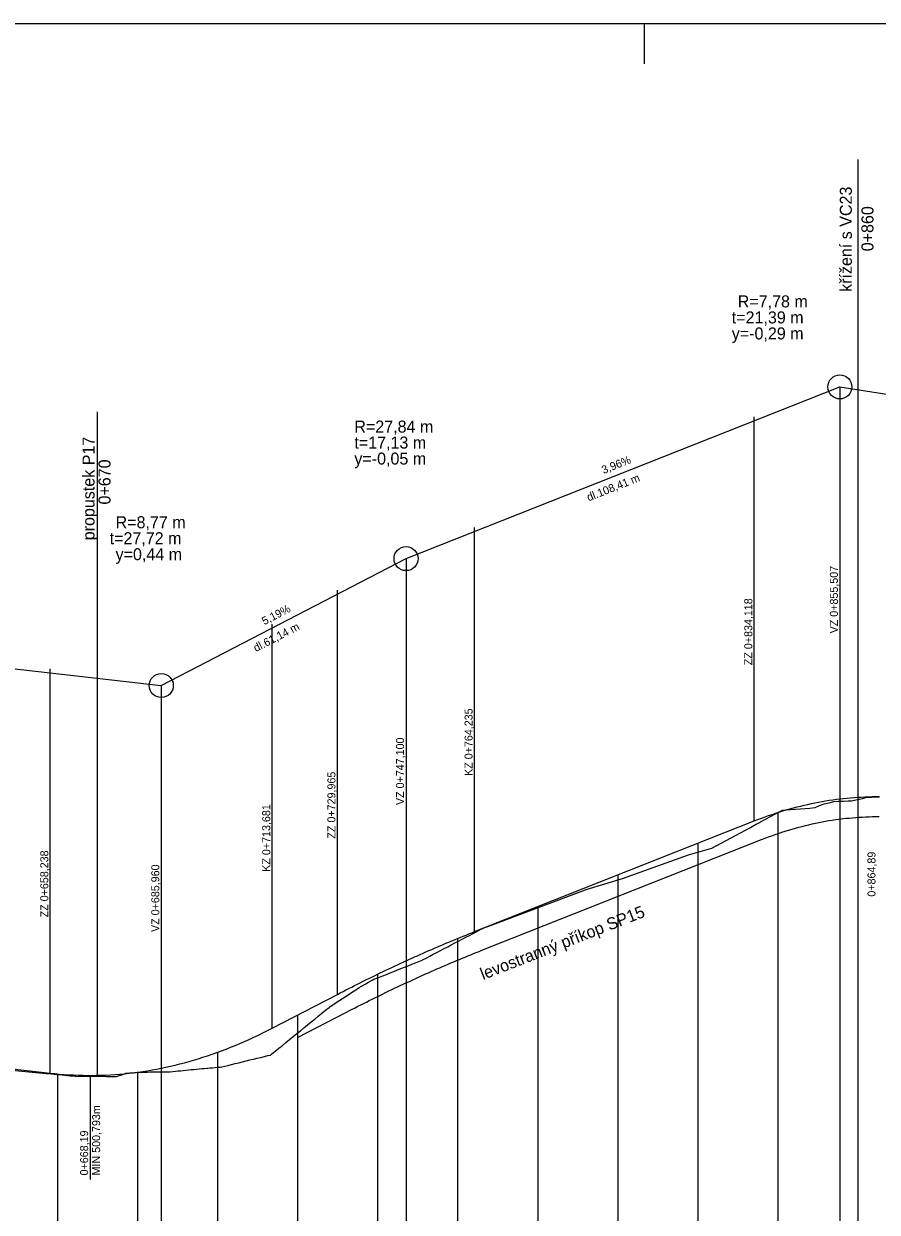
# Model space of a CAD drawing. Extents: x -632716 to -629545, y -1094726 to -1088285.
# Drawn here: x -631800.3 to -631587.1, y -1090081.9 to -1089784.9 of the extents above; entities that cross this region are included whole.
import ezdxf

# ---------------------------------------------------------------- set-up
doc = ezdxf.new("R2010")
doc.units = 0
for name, color, linetype in [('20', 7, 'Continuous'), ('Default', 7, 'Continuous'), ('formát', 7, 'Continuous'), ('PŘÍKOP', 7, 'Continuous'), ('SKLONY_NIVELETA', 7, 'Continuous'), ('SKLONY_POPIS', 7, 'Continuous'), ('TECNY_NIVELETA', 7, 'Continuous'), ('VOZOVKA', 7, 'Continuous')]:
    doc.layers.add(name, color=color, linetype=linetype)

msp = doc.modelspace()

# ---------------------------------------------------------------- linework, layer by layer
at = {"layer": '20'}
for points in [[(-631591.95, -1089978.18), (-631591.95, -1090205.62), (-631591.95, -1090255.62), (-631591.95, -1090195.62)], [(-631611.95, -1089982.01), (-631611.95, -1090205.62), (-631611.95, -1090255.62), (-631611.95, -1090195.62)], [(-631631.95, -1089989.71), (-631631.95, -1090205.62), (-631631.95, -1090255.62), (-631631.95, -1090195.62)], [(-631651.95, -1089997.62), (-631651.95, -1090205.62), (-631651.95, -1090255.62), (-631651.95, -1090195.62)], [(-631671.95, -1090005.54), (-631671.95, -1090205.62), (-631671.95, -1090255.62), (-631671.95, -1090195.62)], [(-631691.95, -1090013.48), (-631691.95, -1090205.62), (-631691.95, -1090255.62), (-631691.95, -1090195.62)], [(-631711.95, -1090022.42), (-631711.95, -1090205.62), (-631711.95, -1090255.62), (-631711.95, -1090195.62)], [(-631731.95, -1090032.62), (-631731.95, -1090205.62), (-631731.95, -1090255.62), (-631731.95, -1090195.62)], [(-631751.95, -1090041.93), (-631751.95, -1090205.62), (-631751.95, -1090255.62), (-631751.95, -1090195.62)], [(-631791.95, -1090047.31), (-631791.95, -1090205.62), (-631791.95, -1090255.62), (-631791.95, -1090195.62)], [(-631771.95, -1090046.9), (-631771.95, -1090205.62), (-631771.95, -1090255.62), (-631771.95, -1090195.62)]]:
    msp.add_lwpolyline(points, dxfattribs=at)
at = {"layer": 'Default'}
for p, q in [((-631687.72, -1090011.77), (-631617.84, -1089984.12)), ((-631738.27, -1090035.9), (-631721.99, -1090027.45)), ((-631847.6, -1090041.02), (-631793.72, -1090047.13))]:
    msp.add_line(p, q, dxfattribs=at)
for points in [[(-631617.84, -1089984.12), (-631616.94, -1089983.77), (-631616.05, -1089983.43), (-631615.16, -1089983.11), (-631614.27, -1089982.79), (-631613.38, -1089982.48), (-631612.49, -1089982.19), (-631611.6, -1089981.9), (-631610.71, -1089981.62), (-631609.82, -1089981.36), (-631608.92, -1089981.1), (-631608.03, -1089980.86), (-631607.14, -1089980.62), (-631606.25, -1089980.4), (-631605.36, -1089980.18), (-631604.47, -1089979.98), (-631603.58, -1089979.78), (-631602.69, -1089979.6), (-631601.79, -1089979.42), (-631600.9, -1089979.26), (-631600.01, -1089979.11), (-631599.12, -1089978.96), (-631598.23, -1089978.83), (-631597.34, -1089978.71), (-631595.56, -1089978.49), (-631594.66, -1089978.4), (-631593.77, -1089978.32), (-631592.88, -1089978.25), (-631591.99, -1089978.18), (-631591.1, -1089978.13), (-631590.21, -1089978.09), (-631589.32, -1089978.06), (-631588.43, -1089978.04), (-631587.53, -1089978.03), (-631586.64, -1089978.03)], [(-631721.99, -1090027.45), (-631721.27, -1090027.08), (-631720.56, -1090026.71), (-631719.85, -1090026.34), (-631719.13, -1090025.98), (-631718.42, -1090025.62), (-631717.7, -1090025.26), (-631716.99, -1090024.9), (-631716.28, -1090024.54), (-631715.56, -1090024.19), (-631714.85, -1090023.83), (-631714.14, -1090023.48), (-631713.42, -1090023.13), (-631712.71, -1090022.79), (-631711.99, -1090022.44), (-631711.28, -1090022.1), (-631710.57, -1090021.75), (-631709.85, -1090021.41), (-631709.14, -1090021.07), (-631708.42, -1090020.74), (-631707.71, -1090020.4), (-631707, -1090020.07), (-631706.28, -1090019.74), (-631705.57, -1090019.41), (-631704.14, -1090018.76), (-631703.43, -1090018.43), (-631702.71, -1090018.11), (-631702, -1090017.79), (-631701.28, -1090017.47), (-631700.57, -1090017.16), (-631699.86, -1090016.84), (-631699.14, -1090016.53), (-631698.43, -1090016.22), (-631697.71, -1090015.91), (-631697, -1090015.6), (-631696.29, -1090015.3), (-631695.57, -1090014.99), (-631694.86, -1090014.69), (-631694.14, -1090014.39), (-631693.43, -1090014.09), (-631692.72, -1090013.8), (-631692, -1090013.5), (-631691.29, -1090013.21), (-631690.57, -1090012.92), (-631689.86, -1090012.63), (-631689.15, -1090012.34), (-631688.43, -1090012.06), (-631687.72, -1090011.77)], [(-631793.72, -1090047.13), (-631792.56, -1090047.26), (-631791.41, -1090047.36), (-631790.25, -1090047.46), (-631789.1, -1090047.53), (-631787.94, -1090047.6), (-631786.78, -1090047.64), (-631785.63, -1090047.68), (-631784.47, -1090047.69), (-631783.32, -1090047.7), (-631782.16, -1090047.68), (-631781.01, -1090047.65), (-631779.85, -1090047.61), (-631778.7, -1090047.55), (-631777.54, -1090047.48), (-631776.39, -1090047.39), (-631775.23, -1090047.28), (-631774.08, -1090047.16), (-631772.92, -1090047.03), (-631771.77, -1090046.88), (-631770.61, -1090046.71), (-631769.46, -1090046.53), (-631768.3, -1090046.33), (-631767.15, -1090046.12), (-631764.84, -1090045.65), (-631763.68, -1090045.4), (-631762.53, -1090045.12), (-631761.37, -1090044.84), (-631760.22, -1090044.53), (-631759.06, -1090044.22), (-631757.91, -1090043.88), (-631756.75, -1090043.54), (-631755.6, -1090043.17), (-631754.44, -1090042.79), (-631753.29, -1090042.4), (-631752.13, -1090041.99), (-631750.98, -1090041.57), (-631749.82, -1090041.13), (-631748.67, -1090040.67), (-631747.51, -1090040.2), (-631746.36, -1090039.72), (-631745.2, -1090039.22), (-631744.05, -1090038.7), (-631742.89, -1090038.17), (-631741.74, -1090037.62), (-631740.58, -1090037.06), (-631739.43, -1090036.49), (-631738.27, -1090035.9)]]:
    msp.add_lwpolyline(points, dxfattribs=at)
at = {"layer": 'formát'}
msp.add_line((-631645.24, -1089794.9), (-631645.24, -1089784.9), dxfattribs=at)
msp.add_lwpolyline([(-632546.83, -1090378.9), (-629545.24, -1090378.9), (-629545.24, -1089784.9), (-632546.83, -1089784.9)], close=True, dxfattribs=at)
at = {"layer": 'PŘÍKOP'}
for p, q in [((-631685.88, -1090016.42), (-631616, -1089988.77)), ((-631731.95, -1090038.25), (-631719.69, -1090031.88))]:
    msp.add_line(p, q, dxfattribs=at)
for points in [[(-631616.02, -1089988.78), (-631615.15, -1089988.44), (-631614.31, -1089988.12), (-631613.46, -1089987.81), (-631612.62, -1089987.51), (-631611.78, -1089987.22), (-631610.93, -1089986.94), (-631610.09, -1089986.67), (-631609.25, -1089986.41), (-631608.41, -1089986.16), (-631607.57, -1089985.92), (-631606.73, -1089985.68), (-631605.89, -1089985.46), (-631605.05, -1089985.25), (-631604.21, -1089985.05), (-631603.38, -1089984.86), (-631602.54, -1089984.67), (-631601.7, -1089984.5), (-631600.86, -1089984.34), (-631600.03, -1089984.18), (-631599.19, -1089984.04), (-631598.35, -1089983.9), (-631597.52, -1089983.78), (-631596.7, -1089983.67), (-631595, -1089983.46), (-631594.18, -1089983.38), (-631593.34, -1089983.3), (-631592.51, -1089983.23), (-631591.67, -1089983.17), (-631590.84, -1089983.13), (-631590.01, -1089983.09), (-631589.17, -1089983.06), (-631588.34, -1089983.04), (-631587.5, -1089983.03), (-631586.67, -1089983.03)], [(-631719.69, -1090031.89), (-631718.98, -1090031.52), (-631718.28, -1090031.16), (-631717.57, -1090030.8), (-631716.87, -1090030.44), (-631716.16, -1090030.08), (-631715.46, -1090029.72), (-631714.75, -1090029.37), (-631714.05, -1090029.02), (-631713.34, -1090028.67), (-631712.64, -1090028.32), (-631711.93, -1090027.97), (-631711.23, -1090027.63), (-631710.52, -1090027.28), (-631709.82, -1090026.94), (-631709.11, -1090026.6), (-631708.41, -1090026.27), (-631707.71, -1090025.93), (-631707, -1090025.6), (-631706.3, -1090025.26), (-631705.59, -1090024.93), (-631704.89, -1090024.6), (-631704.18, -1090024.28), (-631703.48, -1090023.95), (-631702.07, -1090023.31), (-631701.37, -1090022.99), (-631700.66, -1090022.67), (-631699.96, -1090022.36), (-631699.25, -1090022.04), (-631698.55, -1090021.73), (-631697.84, -1090021.42), (-631697.14, -1090021.11), (-631696.44, -1090020.81), (-631695.73, -1090020.5), (-631695.03, -1090020.2), (-631694.32, -1090019.9), (-631693.62, -1090019.6), (-631692.92, -1090019.3), (-631692.21, -1090019), (-631691.51, -1090018.71), (-631690.8, -1090018.42), (-631690.1, -1090018.13), (-631689.4, -1090017.84), (-631688.69, -1090017.55), (-631687.99, -1090017.27), (-631687.29, -1090016.98), (-631686.58, -1090016.7), (-631685.87, -1090016.42)]]:
    msp.add_lwpolyline(points, dxfattribs=at)
at = {"layer": 'SKLONY_NIVELETA'}
for p, q in [((-631591.95, -1089818.79), (-631591.95, -1089978.18)), ((-631704.85, -1089918.56), (-631596.45, -1089875.65)), ((-631596.45, -1089875.65), (-631596.45, -1090255.62)), ((-631596.45, -1089875.65), (-631534.11, -1089885.28)), ((-631765.99, -1089950.28), (-631704.85, -1089918.56)), ((-631704.85, -1089918.56), (-631704.85, -1090255.62)), ((-631884.73, -1089936.8), (-631765.99, -1089950.28)), ((-631765.99, -1089950.28), (-631765.99, -1090255.62)), ((-631687.72, -1090011.77), (-631617.84, -1089984.12)), ((-631738.27, -1090035.9), (-631721.99, -1090027.45)), ((-631847.6, -1090041.02), (-631793.72, -1090047.13))]:
    msp.add_line(p, q, dxfattribs=at)
for points in [[(-631617.84, -1089984.12), (-631616.94, -1089983.77), (-631616.05, -1089983.43), (-631615.16, -1089983.11), (-631614.27, -1089982.79), (-631613.38, -1089982.48), (-631612.49, -1089982.19), (-631611.6, -1089981.9), (-631610.71, -1089981.62), (-631609.82, -1089981.36), (-631608.92, -1089981.1), (-631608.03, -1089980.86), (-631607.14, -1089980.62), (-631606.25, -1089980.4), (-631605.36, -1089980.18), (-631604.47, -1089979.98), (-631603.58, -1089979.78), (-631602.69, -1089979.6), (-631601.79, -1089979.42), (-631600.9, -1089979.26), (-631600.01, -1089979.11), (-631599.12, -1089978.96), (-631598.23, -1089978.83), (-631597.34, -1089978.71), (-631595.56, -1089978.49), (-631594.66, -1089978.4), (-631593.77, -1089978.32), (-631592.88, -1089978.25), (-631591.99, -1089978.18), (-631591.1, -1089978.13), (-631590.21, -1089978.09), (-631589.32, -1089978.06), (-631588.43, -1089978.04), (-631587.53, -1089978.03), (-631586.64, -1089978.03)], [(-631721.99, -1090027.45), (-631721.27, -1090027.08), (-631720.56, -1090026.71), (-631719.85, -1090026.34), (-631719.13, -1090025.98), (-631718.42, -1090025.62), (-631717.7, -1090025.26), (-631716.99, -1090024.9), (-631716.28, -1090024.54), (-631715.56, -1090024.19), (-631714.85, -1090023.83), (-631714.14, -1090023.48), (-631713.42, -1090023.13), (-631712.71, -1090022.79), (-631711.99, -1090022.44), (-631711.28, -1090022.1), (-631710.57, -1090021.75), (-631709.85, -1090021.41), (-631709.14, -1090021.07), (-631708.42, -1090020.74), (-631707.71, -1090020.4), (-631707, -1090020.07), (-631706.28, -1090019.74), (-631705.57, -1090019.41), (-631704.14, -1090018.76), (-631703.43, -1090018.43), (-631702.71, -1090018.11), (-631702, -1090017.79), (-631701.28, -1090017.47), (-631700.57, -1090017.16), (-631699.86, -1090016.84), (-631699.14, -1090016.53), (-631698.43, -1090016.22), (-631697.71, -1090015.91), (-631697, -1090015.6), (-631696.29, -1090015.3), (-631695.57, -1090014.99), (-631694.86, -1090014.69), (-631694.14, -1090014.39), (-631693.43, -1090014.09), (-631692.72, -1090013.8), (-631692, -1090013.5), (-631691.29, -1090013.21), (-631690.57, -1090012.92), (-631689.86, -1090012.63), (-631689.15, -1090012.34), (-631688.43, -1090012.06), (-631687.72, -1090011.77)], [(-631793.72, -1090047.13), (-631792.56, -1090047.26), (-631791.41, -1090047.36), (-631790.25, -1090047.46), (-631789.1, -1090047.53), (-631787.94, -1090047.6), (-631786.78, -1090047.64), (-631785.63, -1090047.68), (-631784.47, -1090047.69), (-631783.32, -1090047.7), (-631782.16, -1090047.68), (-631781.01, -1090047.65), (-631779.85, -1090047.61), (-631778.7, -1090047.55), (-631777.54, -1090047.48), (-631776.39, -1090047.39), (-631775.23, -1090047.28), (-631774.08, -1090047.16), (-631772.92, -1090047.03), (-631771.77, -1090046.88), (-631770.61, -1090046.71), (-631769.46, -1090046.53), (-631768.3, -1090046.33), (-631767.15, -1090046.12), (-631764.84, -1090045.65), (-631763.68, -1090045.4), (-631762.53, -1090045.12), (-631761.37, -1090044.84), (-631760.22, -1090044.53), (-631759.06, -1090044.22), (-631757.91, -1090043.88), (-631756.75, -1090043.54), (-631755.6, -1090043.17), (-631754.44, -1090042.79), (-631753.29, -1090042.4), (-631752.13, -1090041.99), (-631750.98, -1090041.57), (-631749.82, -1090041.13), (-631748.67, -1090040.67), (-631747.51, -1090040.2), (-631746.36, -1090039.72), (-631745.2, -1090039.22), (-631744.05, -1090038.7), (-631742.89, -1090038.17), (-631741.74, -1090037.62), (-631740.58, -1090037.06), (-631739.43, -1090036.49), (-631738.27, -1090035.9)]]:
    msp.add_lwpolyline(points, dxfattribs=at)
for centre in [(-631596.45, -1089875.65), (-631704.85, -1089918.56), (-631765.99, -1089950.28)]:
    msp.add_circle(centre, 3, dxfattribs=at)
at = {"layer": 'TECNY_NIVELETA'}
for p, q in [((-631596.45, -1089875.65), (-631596.45, -1089875.65)), ((-631781.95, -1090047.68), (-631781.95, -1089881.89)), ((-631617.84, -1089984.12), (-631617.84, -1089883.12)), ((-631687.72, -1090011.77), (-631687.72, -1089910.77)), ((-631704.85, -1089918.56), (-631704.85, -1089918.56)), ((-631721.99, -1090027.45), (-631721.99, -1089926.45)), ((-631738.27, -1090035.9), (-631738.27, -1089934.9)), ((-631793.72, -1090047.13), (-631793.72, -1089946.13)), ((-631765.99, -1089950.28), (-631765.99, -1089950.28)), ((-631783.77, -1090047.7), (-631783.77, -1090073.7))]:
    msp.add_line(p, q, dxfattribs=at)
at = {"layer": 'VOZOVKA'}
msp.add_lwpolyline([(-631821.69, -1090044.62), (-631794.79, -1090047.19), (-631794.12, -1090047.25), (-631793.45, -1090047.32), (-631792.79, -1090047.38), (-631792.12, -1090047.45), (-631791.45, -1090047.51), (-631790.79, -1090047.58), (-631790.12, -1090047.64), (-631789.45, -1090047.71), (-631788.79, -1090047.78), (-631788.12, -1090047.85), (-631787.45, -1090047.93), (-631787.36, -1090047.94), (-631786.79, -1090047.92), (-631786.12, -1090047.9), (-631785.45, -1090047.89), (-631784.79, -1090047.88), (-631784.22, -1090047.87), (-631784.15, -1090047.87), (-631783.51, -1090047.87), (-631782.87, -1090047.88), (-631782.24, -1090047.89), (-631781.6, -1090047.9), (-631780.96, -1090047.91), (-631780.32, -1090047.92), (-631779.69, -1090047.94), (-631779.05, -1090047.96), (-631778.41, -1090047.97), (-631777.77, -1090047.99), (-631777.24, -1090048.01), (-631777.14, -1090047.98), (-631776.5, -1090047.76), (-631775.86, -1090047.55), (-631775.39, -1090047.39), (-631775.22, -1090047.32), (-631774.82, -1090047.14), (-631774.59, -1090047.12), (-631773.95, -1090047.07), (-631773.31, -1090047.02), (-631772.67, -1090046.97), (-631772.04, -1090046.92), (-631771.68, -1090046.9), (-631771.4, -1090046.89), (-631770.76, -1090046.88), (-631770.13, -1090046.87), (-631769.49, -1090046.86), (-631768.85, -1090046.85), (-631768.21, -1090046.85), (-631768.03, -1090046.85), (-631767.58, -1090046.84), (-631766.94, -1090046.83), (-631766.3, -1090046.82), (-631765.66, -1090046.81), (-631765.03, -1090046.81), (-631764.39, -1090046.8), (-631763.89, -1090046.8), (-631763.75, -1090046.79), (-631763.11, -1090046.72), (-631762.48, -1090046.65), (-631761.84, -1090046.59), (-631761.2, -1090046.52), (-631760.53, -1090046.46), (-631759.87, -1090046.39), (-631759.2, -1090046.32), (-631758.53, -1090046.26), (-631757.87, -1090046.19), (-631757.2, -1090046.13), (-631756.53, -1090046.06), (-631755.87, -1090046), (-631755.2, -1090045.94), (-631754.53, -1090045.87), (-631754.39, -1090045.86), (-631753.87, -1090045.82), (-631753.2, -1090045.77), (-631752.53, -1090045.72), (-631751.87, -1090045.67), (-631751.2, -1090045.62), (-631750.83, -1090045.6), (-631749.33, -1090045.22), (-631748.42, -1090044.99), (-631747.51, -1090044.76), (-631746.6, -1090044.53), (-631745.69, -1090044.31), (-631744.78, -1090044.08), (-631743.87, -1090043.85), (-631742.96, -1090043.63), (-631742.06, -1090043.41), (-631741.15, -1090043.19), (-631740.24, -1090042.98), (-631739.33, -1090042.76), (-631738.74, -1090042.63), (-631738.71, -1090042.62), (-631738.71, -1090042.62), (-631738.43, -1090042.39), (-631737.53, -1090041.66), (-631736.63, -1090040.92), (-631735.74, -1090040.19), (-631734.84, -1090039.46), (-631733.94, -1090038.72), (-631733.04, -1090037.99), (-631732.14, -1090037.26), (-631731.25, -1090036.53), (-631730.35, -1090035.8), (-631729.45, -1090035.07), (-631728.55, -1090034.34), (-631727.66, -1090033.61), (-631726.76, -1090032.88), (-631725.86, -1090032.16), (-631724.96, -1090031.43), (-631724.06, -1090030.71), (-631723.81, -1090030.51), (-631723.17, -1090030.09), (-631722.27, -1090029.5), (-631721.37, -1090028.92), (-631720.47, -1090028.33), (-631719.57, -1090027.74), (-631718.68, -1090027.14), (-631717.78, -1090026.55), (-631716.88, -1090025.96), (-631716.58, -1090025.75), (-631715.98, -1090025.42), (-631715.09, -1090024.91), (-631714.19, -1090024.41), (-631713.29, -1090023.9), (-631712.89, -1090023.67), (-631712.39, -1090023.49), (-631711.49, -1090023.14), (-631710.6, -1090022.8), (-631709.7, -1090022.45), (-631708.8, -1090022.09), (-631707.9, -1090021.72), (-631707, -1090021.35), (-631706.29, -1090021.05), (-631706.11, -1090020.99), (-631705.21, -1090020.64), (-631704.31, -1090020.3), (-631703.41, -1090019.94), (-631702.52, -1090019.58), (-631701.62, -1090019.22), (-631700.85, -1090018.9), (-631700.72, -1090018.83), (-631699.82, -1090018.37), (-631698.92, -1090017.9), (-631698.03, -1090017.43), (-631697.13, -1090016.96), (-631696.23, -1090016.49), (-631695.33, -1090016.02), (-631694.43, -1090015.55), (-631693.53, -1090015.08), (-631692.62, -1090014.6), (-631691.71, -1090014.13), (-631690.8, -1090013.65), (-631689.89, -1090013.17), (-631688.98, -1090012.7), (-631688.07, -1090012.22), (-631687.16, -1090011.75), (-631686.25, -1090011.27), (-631685.34, -1090010.8), (-631685.28, -1090010.76), (-631684.43, -1090010.45), (-631659.55, -1090001.17), (-631650.78, -1089998.46), (-631634.25, -1089992.6), (-631628.42, -1089990.88), (-631622.51, -1089987.72), (-631621.26, -1089987.05), (-631620.01, -1089986.38), (-631618.76, -1089985.71), (-631617.51, -1089985.04), (-631616.52, -1089984.51), (-631616.26, -1089984.37), (-631615.01, -1089983.7), (-631613.76, -1089983.02), (-631612.51, -1089982.35), (-631611.26, -1089981.67), (-631610.77, -1089981.4), (-631610.01, -1089981.35), (-631608.76, -1089981.26), (-631607.51, -1089981.17), (-631606.32, -1089981.08), (-631605.12, -1089980.98), (-631603.93, -1089980.88), (-631602.74, -1089980.77), (-631602.6, -1089980.76), (-631601.55, -1089980.25), (-631601.32, -1089980.14), (-631600.36, -1089979.87), (-631599.17, -1089979.56), (-631598.22, -1089979.32), (-631597.98, -1089979.29), (-631596.78, -1089979.19), (-631595.59, -1089979.13), (-631594.4, -1089979.09), (-631593.52, -1089979.1), (-631593.21, -1089979.03), (-631592.02, -1089978.76), (-631590.83, -1089978.48), (-631589.64, -1089978.2), (-631589.44, -1089978.15), (-631588.44, -1089978.14), (-631587.25, -1089978.12), (-631586.53, -1089978.12)], dxfattribs=at)

# ---------------------------------------------------------------- texts
at = {"layer": 'SKLONY_POPIS'}
for s, height, rotation, p in [('křížení s VC23', 3, 90, (-631593.47, -1089851.9)), ('0+860', 3, 90, (-631588.07, -1089841.75)), ('propustek P17', 3, 90, (-631782.67, -1089913.97)), ('0+670', 3, 90, (-631778.67, -1089905.04)), ('3,96%', 2, 21.5914, (-631655.51, -1089897.42)), ('dl.108,41 m', 2, 21.5914, (-631659.21, -1089904.26)), ('VZ 0+855,507', 2, 90, (-631596.95, -1089937.24)), ('5,19%', 2, 27.4219, (-631740.23, -1089935.22)), ('ZZ 0+834,118', 2, 90, (-631618.34, -1089945.2)), ('dl.61,14 m', 2, 27.4219, (-631742.33, -1089941.94)), ('KZ 0+764,235', 2, 90, (-631688.22, -1089972.86)), ('VZ 0+747,100', 2, 90, (-631705.35, -1089980.14)), ('ZZ 0+729,965', 2, 90, (-631722.49, -1089988.53)), ('KZ 0+713,681', 2, 90, (-631738.77, -1089996.81)), ('ZZ 0+658,238', 2, 90, (-631794.22, -1090008.21)), ('0+864,89', 2, 90, (-631587.56, -1090003.03)), ('VZ 0+685,960', 2, 90, (-631766.49, -1090011.86)), ('levostranný příkop SP15', 3, 21.3787, (-631685.6, -1090023.9)), ('MIN 500,793m', 2, 90, (-631781.27, -1090072.7)), ('0+668,19', 2, 90, (-631784.27, -1090072.7))]:
    msp.add_text(s, height=height, rotation=rotation, dxfattribs=at).set_placement(p)
for s, p in [('R=7,78 m', (-631621.98, -1089855.78)), ('t=21,39 m', (-631623.47, -1089859.78)), ('y=-0,29 m', (-631623.47, -1089863.78)), ('R=27,84 m', (-631717.76, -1089887.06)), ('t=17,13 m', (-631717.76, -1089891.06)), ('y=-0,05 m', (-631717.76, -1089895.06)), ('R=8,77 m', (-631777.41, -1089910.96)), ('t=27,72 m', (-631778.9, -1089914.96)), ('y=0,44 m', (-631777.41, -1089918.96))]:
    msp.add_text(s, height=3, dxfattribs=at).set_placement(p)

doc.saveas('drawing.dxf')
